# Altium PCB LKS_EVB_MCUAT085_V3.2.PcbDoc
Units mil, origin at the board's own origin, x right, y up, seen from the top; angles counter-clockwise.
Board outline 2625 x 1560 mil, 2 copper layers (Top Layer, Bottom Layer); 67 components, 81 nets, 250 pads, 65 vias.
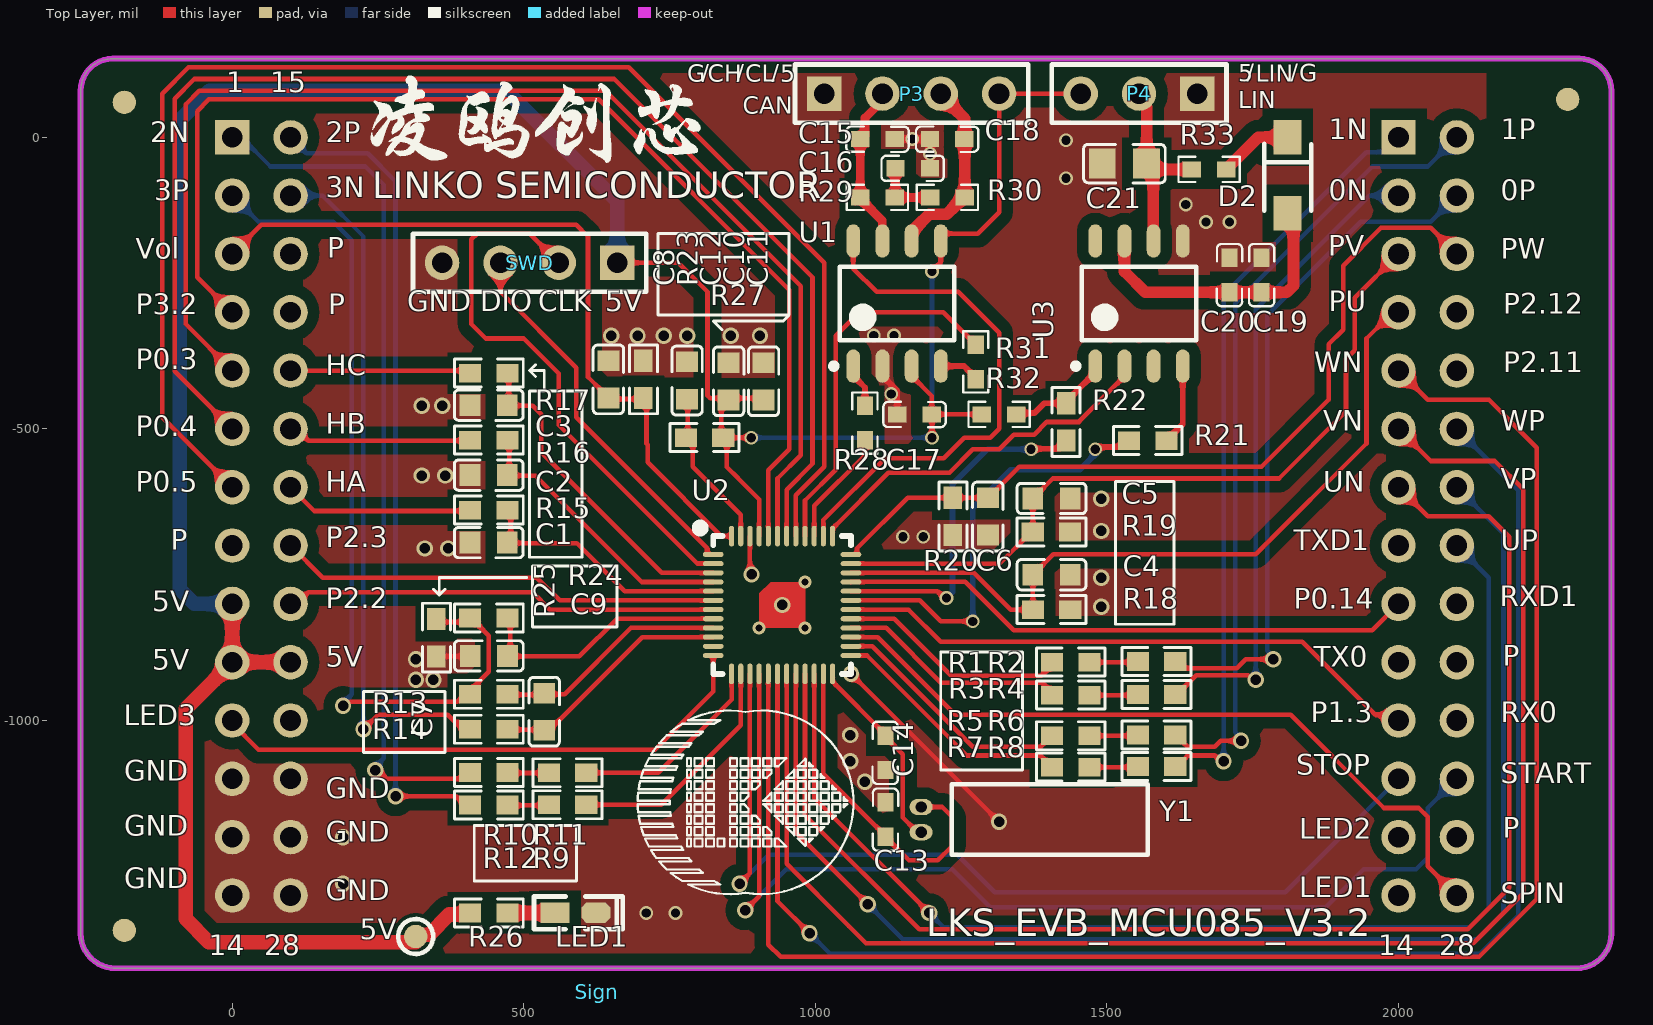
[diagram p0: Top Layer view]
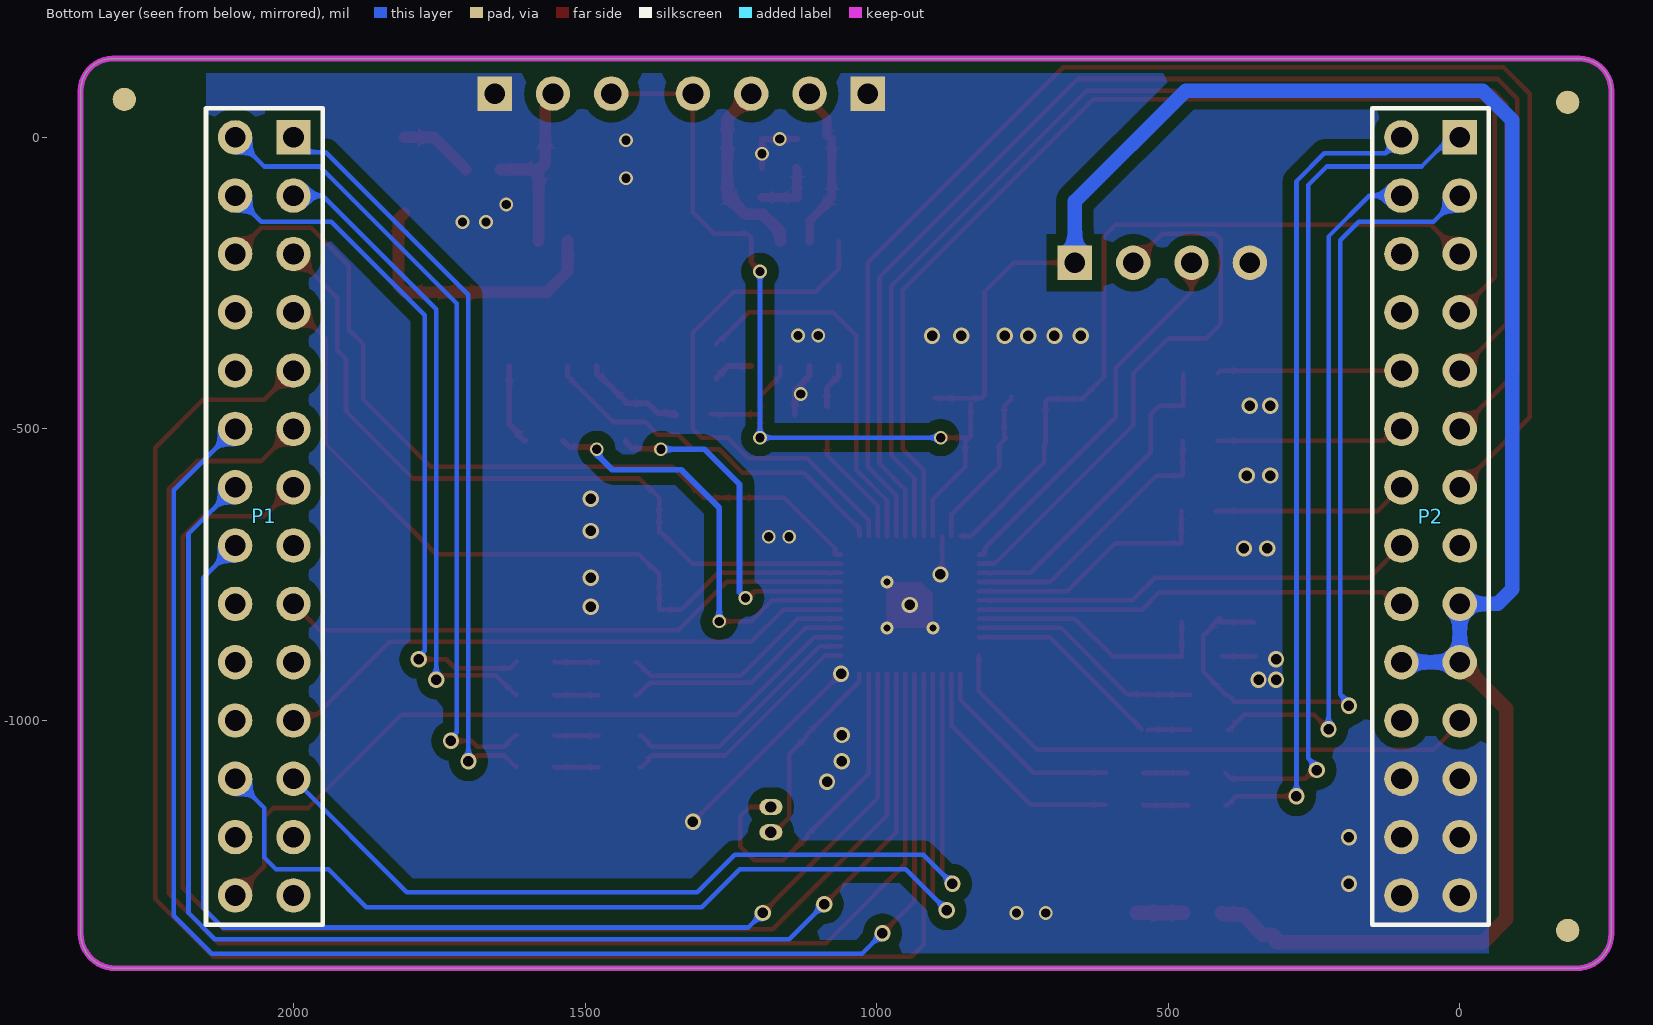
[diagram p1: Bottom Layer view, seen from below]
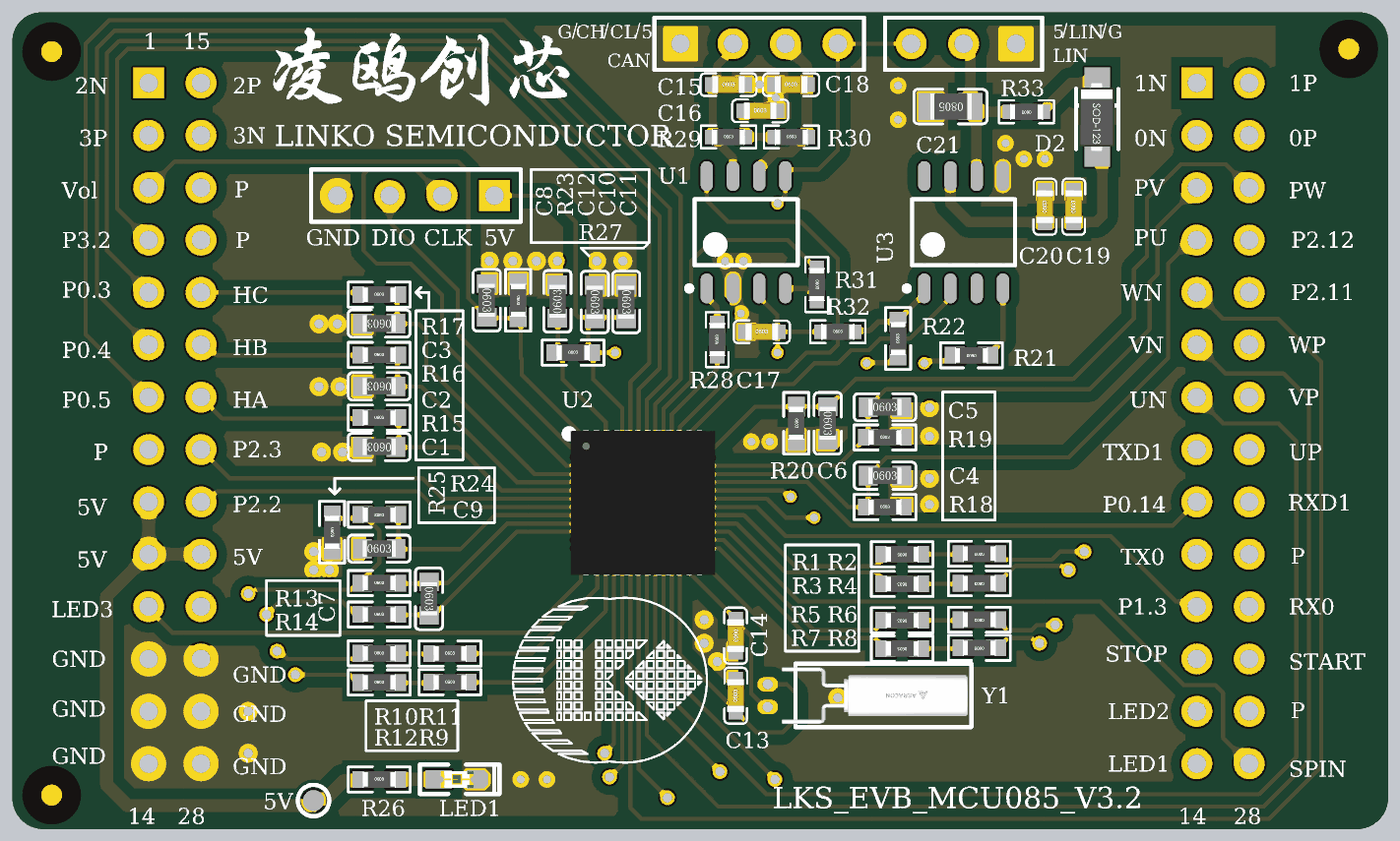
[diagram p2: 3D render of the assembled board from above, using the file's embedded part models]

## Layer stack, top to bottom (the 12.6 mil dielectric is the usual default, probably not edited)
Top Solder: solder mask 0.4, Solder Resist, Dk 3.5
Top Layer: signal copper 1.4
Dielectric1: dielectric 12.6, FR-4, Dk 4.8
Bottom Layer: signal copper 1.4
Bottom Solder: solder mask 0.4, Solder Resist, Dk 3.5

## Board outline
-260,-1365 ccw(c-200,-1365) -200,-1425 2305,-1425 ccw(c2305,-1365) 2365,-1365 2365,80 ccw(c2310,80) 2310,135 -205,135 ccw(c-205,80) -260,80

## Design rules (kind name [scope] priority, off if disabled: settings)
Clearance Clearance_2 [InPolygon] p1: gap=20 ignorepadtopadclearanceinfootprint=FALSE except(0: Arc-Hole Track-Hole SMDPad-Hole THPad-Hole Via-Hole Fill-Hole Poly-Hole Region-Hole Text-Hole)
Clearance Clearance_1 [All] p2: gap=4 ignorepadtopadclearanceinfootprint=FALSE except(0: Arc-Hole Track-Hole SMDPad-Hole THPad-Hole Via-Hole Fill-Hole Poly-Hole Region-Hole Text-Hole)
ComponentClearance [All] p1: gap=0 collisioncheckmode=3 verticalgap=0 showdistances=FALSE
FabricationTestpoint [(IsPad And (OnTopLayer Or OnBottomLayer))] p1: side=3 testpointundercomponent=TRUE minsize=40 maxsize=100 preferedsize=60 minholesize=0 maxholesize=40 preferedholesize=32 testpointgrid=1 allowsidetop=TRUE allowsidebottom=TRUE usegrid=TRUE gridtolerance=0.01
HoleSize [All] p1: absolutevalues=TRUE maxlimit=100 minlimit=0 maxpercent=80.000 minpercent=20.000
PolygonConnect [All] p1: connectstyle=Direct reliefconductorwidth=10 reliefentries=4 polygonreliefangle="90 Angle" airgapwidth=10
RoutingVias [All] p1: holewidth=28 width=50 viastyle="Through Hole" minholewidth=0 minwidth=10 maxholewidth=28 maxwidth=50
SilkToSolderMaskClearance SilkscreenOverComponentPads [IsPad] p1: minsilkscreentomaskgap=10 clearancetoexposedcopper=TRUE
SolderMaskExpansion [All] p1: expansion=4 istentingtop=FALSE
Width [All] p1: maxlimit=100 minlimit=3.94 preferedwidth=7.87
26 further rules are at their usual default settings.

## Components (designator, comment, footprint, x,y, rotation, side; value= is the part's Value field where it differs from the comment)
5V "TestP" TP-40 315,-1370 r0 top
C1 "10nF/16V" 0603C 439.85,-694.97 r180 top
C2 "10nF/16V" 0603C 439.85,-579.25 r180 top
C3 "10nF/16V" 0603C 439.85,-459.25 r180 top
C4 "1nF/16V" 0603C 1405,-750 r0 top
C5 "1nF/16V" 0603C 1405,-619.25 r0 top
C6 "1nF/16V" 0603C 1295.75,-650 r270 top
C7 "1nF/16V" 0603C 535,-985 r270 top
C8 "100nF/50V" 0603C 645,-415 r270 top
C9 "1nF/16V" 0603C 439.98,-889.25 r0 top
C10 "10uF/10V" 0603C 851.24,-418.31 r270 top
C11 "100nF/50V" 0603C 911.24,-418.31 r270 top
C12 "100nF/50V" 0603C 780,-417 r90 top
C13 "4.7nF/50V" "0603C _1" 1120,-1170 r90 top
C14 "4.7nF/50V" "0603C _1" 1120,-1055.47 r270 top
C15 "30pF" "0603C _1" 1106.43,-3 r0 top
C16 "4.7nF/50V" "0603C _1" 1166.91,-53 r0 top
C17 "100nF" "0603C _1" 1170,-475 r0 top
C18 "30pF" "0603C _1" 1225.96,-3 r0 top
C19 "2.2uF/25V" "0603C _1" 1765.08,-236.22 r90 top
C20 "100nF" "0603C _1" 1710.08,-236.22 r90 top
C21 "1nF" 0805C 1530,-45 r180 top
D2 "1N4148" SOD123 1810,-65 r90 top
LED1 "LED" "LED 0603R" 588.51,-1330 r0 top
P1 "Header 14X2A" HDR2X14_CEN 2000,0 r270 bottom
P2 "Header 14X2A" HDR2X14_CEN 0,0 r270 bottom locked
P3 "Header 4" HDR1X4 1015,75 r0 top
P4 "Header 3" HDR1X3 1655,75 r180 top
R1 "20K1%" 0603R 1437.85,-900 r180 top value=K
R2 "20K1%" 0603R 1585,-898.83 r180 top value=K
R3 "20K1%" 0603R 1437.85,-956.59 r180 top value=K
R4 "20K1%" 0603R 1585,-955.42 r180 top value=K
R5 "20K1%" 0603R 1437.85,-1026.17 r180 top value=K
R6 "20K1%" 0603R 1585,-1025 r180 top value=K
R7 "20K1%" 0603R 1437.85,-1080 r180 top value=K
R8 "20K1%" 0603R 1585,-1078.83 r180 top value=K
R9 "20K1%" 0603R 575.01,-1144.52 r0 top value=K
R10 "20K1%" 0603R 440,-1144.85 r0 top value=K
R11 "20K1%" 0603R 575.01,-1089.56 r0 top value=K
R12 "20K1%" 0603R 440,-1089.25 r0 top value=K
R13 "1K1%" 0603R 440,-955 r0 top value=K
R14 "1K1%" 0603R 440,-1015 r0 top value=K
R15 "2K" 0603R 440,-639.25 r0 top value=K
R16 "2K" 0603R 440,-519.25 r0 top value=K
R17 "2K" 0603R 440,-404.25 r0 top value=K
R18 "1K1%" 0603R 1405,-810 r0 top value=K
R19 "1K1%" 0603R 1404.85,-676.86 r0 top value=K
R20 "1K1%" 0603R 1235.75,-650 r270 top value=K
R21 "10R" 0603R 1570,-520 r180 top value=K
R22 "10R" 0603R 1430,-488 r90 top value=K
R23 "1K1%" 0603R 705,-415 r270 top value=K
R24 "1K1%" 0603R 440,-824.25 r180 top value=K
R25 "10R" 0603R 350,-858 r270 top value=K
R26 "330R" 0603R 440,-1330 r0 top value=330
R27 "20K1%" 0603R 810,-515 r0 top value=K
R28 "10R" 0603R_1 1085,-490 r90 top value=K
R29 "60R/1%" 0603R_1 1106.43,-103 r0 top value=K
R30 "60R/1%" 0603R_1 1226.43,-103 r0 top value=K
R31 "10R" 0603R_1 1275,-385 r270 top value=K
R32 "10K" 0603R_1 1315,-475 r0 top value=K
R33 "1K" 0603R_1 1675,-55 r180 top value=K
Sign "LKS_sign" LKS_LOGO2 625,-1465 r0 top
SWD "Header 4" HDR1X4 660,-215.05 r180 top
U1 "SIT1051T/3" SOP-8N 1140,-285 r90 top
U2 "LKS32AT85C8Q9" LKS085-QFN48 942.87,-801.89 r0 top
U3 "SIT1027Q" SOP-8N 1555,-285 r90 top
Y1 "WTL3T45412LZ" DT-38 1445,-1170 r180 top (schematic designator Y?)

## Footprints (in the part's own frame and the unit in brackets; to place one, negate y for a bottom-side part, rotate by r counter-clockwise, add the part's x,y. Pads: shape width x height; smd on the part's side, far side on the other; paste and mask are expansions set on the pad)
0603C [mm]
  rect 0.9x0.95 smd: 1(-0.813,0) 2(0.813,0)
  silkscreen extent -1.5,-0.66 1.5,0.66, body extent -0.8,-0.4 0.8,0.4, height 0.45
"0603C _1" [mm]
  rect 0.8x0.7 smd: 1(-0.75,0) 2(0.75,0)
  silkscreen extent -1.36,-0.56 1.36,0.55, body extent -0.8,-0.41 0.8,0.41, height 0.81
0603R [mil]
  rect 38x32 smd: 1(-32,0) 2(32,0)
  silkscreen extent -59,-24 59,24, body extent -31,-16 32,16, height 16
0603R_1 [mm]
  rect 0.8x0.7 smd: 1(-0.75,0) 2(0.75,0)
  silkscreen extent -1.33,-0.55 1.33,0.55, body extent -0.8,-0.4 0.8,0.4, height 0.4
0805C [mil]
  rect 46x51.18 smd: 1(-38,0) 2(38,0)
  silkscreen extent -70,-33 70,33, body extent -40,-25 38,25, height 22
DT-38 [mm]
  oval 1x0.7 hole 0.5 paste+0 mask+0: 1(6.7,0.55) 2(6.7,-0.55)
  silkscreen extent -3.18,-1.55 5.36,1.52, body extent -3.2,-1.85 6.73,1.85, height 0.25
HDR1X3 [mm] "Connector; Header; 3 Position"
  rect 1.5x1.5 hole 0.9: 1(0,0)
  round 1.5 hole 0.9: 2(2.54,0) 3(5.08,0)
  silkscreen extent -1.27,-1.27 6.35,1.27
HDR1X4 [mm] "Connector; Header; 4 Position"
  rect 1.5x1.5 hole 0.9: 1(0,0)
  round 1.5 hole 0.9: 2(2.54,0) 3(5.08,0) 4(7.62,0)
  silkscreen extent -1.27,-1.27 8.89,1.27
HDR2X14_CEN [mm] "Connector; Header; 14x2 Position"
  rect 1.5x1.5 hole 0.9: 1(0,0)
  round 1.5 hole 0.9: 2(2.54,0) 3(5.08,0) 4(7.62,0) 5(10.16,0) 6(12.7,0) 7(15.24,0) 8(17.78,0) 9(20.32,0) 10(22.86,0) 11(25.4,0) 12(27.94,0) 13(30.48,0) 14(33.02,0) 15(0,-2.54) 16(2.54,-2.54) 17(5.08,-2.54) 18(7.62,-2.54) 19(10.16,-2.54) 20(12.7,-2.54) 21(15.24,-2.54) 22(17.78,-2.54) 23(20.32,-2.54) 24(22.86,-2.54) 25(25.4,-2.54) 26(27.94,-2.54) 27(30.48,-2.54) 28(33.02,-2.54)
  silkscreen extent -1.27,-3.81 34.29,1.27
"LED 0603R" [mil] "红色0"
  rect 50x35 smd: 1(-35,0.26)
  oct 50x35 smd: 2(35,0.26)
  silkscreen extent -71,-28 81,28, body extent -31,-16 31,16, height 18
LKS085-QFN48 [mm]
  round 0.025 smd: 0(0,0)
  oval 0.22x0.9 smd: 1(-2.2,3) 2(-1.8,3) 3(-1.4,3) 4(-1,3) 5(-0.6,3) 6(-0.2,3) 7(0.2,3) 8(0.6,3) 9(1,3) 10(1.4,3) 11(1.8,3) 12(2.2,3) 25(2.2,-3) 26(1.8,-3) 27(1.4,-3) 28(1,-3) 29(0.6,-3) 30(0.2,-3) 31(-0.2,-3) 32(-0.6,-3) 33(-1,-3) 34(-1.4,-3) 35(-1.8,-3) 36(-2.2,-3)
  oval 0.9x0.22 smd: 13(3,2.2) 14(3,1.8) 15(3,1.4) 16(3,1) 17(3,0.6) 18(3,0.2) 19(3,-0.2) 20(3,-0.6) 21(3,-1) 22(3,-1.4) 23(3,-1.8) 24(3,-2.2) 37(-3,-2.2) 38(-3,-1.8) 39(-3,-1.4) 40(-3,-1) 41(-3,-0.6) 42(-3,-0.2) 43(-3,0.2) 44(-3,0.6) 45(-3,1) 46(-3,1.4) 47(-3,1.8) 48(-3,2.2)
  Top Layer region: -1,-1 -1,0.5 -0.5,1 1,1 1,-1
  silkscreen extent -3.68,-3 3,3.47, body extent -3.51,-3.51 3.51,3.51, height 0.78
LKS_LOGO2 [mil]
  silkscreen extent 70,167 440,482
SOD123 [mm] "SOD-123; 2 Leads; Body 2.7 x 1.6 mm, (LxW)"
  rect 1.5x1.22 smd: 1(-1.65,0) 2(1.65,0)
  silkscreen extent -1.55,-1.03 1.38,1.02, body extent -1.93,-0.82 1.93,0.87, height 0.92
SOP-8N [mm]
  oval 1.45x0.6 smd: 1(-2.725,1.905) 2(-2.725,0.635) 3(-2.725,-0.635) 4(-2.725,-1.905) 5(2.725,-1.905) 6(2.725,-0.635) 7(2.725,0.635) 8(2.725,1.905)
  silkscreen extent -2.85,-2.5 1.6,2.88, body extent -2,-2.5 2,2.5, height 1.7
TP-40 [mil] "?"
  round 40 smd: 1(-0.39,-0.39)
  silkscreen extent -30,-30 30,30

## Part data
5V: "测试点"
C1 C2 C3 C4 C5 C6: library part CAP, "Capacitor"
C7 C8 C9 C10 C11 C12: library part C, "Capacitor"
C13 C14 C15 C16 C17 C18 C19 C20 C21: library part Capacitor, "Capacitor --贴片电容"
D2: library part Diode, "Default Diode", PackageDocument=Sep-1996
LED1: "发光二极管"
P1 P2: "Header, 14-Pin, Dual row"
P3 SWD: "Header, 4-Pin"
P4: "Header, 3-Pin"
R1 R2 R3 R4 R5 R6 R7 R8 R9 R10 R11 R12 R13 R14 R15 R16 R17 R18 R19 R20 R21 R22 R23 R24 R25 R26 R27 R28 R29 R30 R31 R32 R33: library part Res, "Resistor"
Sign: "凌鸥公司图标/丝印"
U1: "SIT芯力特CAN芯片  sop-8"
U2: library part LKS085, "车规芯片"
U3: library part SIT1021T, "SIT芯力特LIN芯片  SOP-8"
Y1: library part Crystal, "CRYSTAL 圆柱体晶振 频率：4MHz 频率公差：±20ppm 频率稳定度：±20ppm 负载电容：20pF 等效串联电阻(ESR)：150Ω 工作温度：-20℃~+70℃", Case/Package=Radial, ESR (Equivalent Series Resistance)=50kR, Frequency=32.768kHz, Frequency Stability=-0.034ppm, Frequency Tolerance=20ppm, Load Capacitance=12.5pF, Manufacturer=Abracon, Manufacturer Part Number=AB26TRB-32.768KHZ-T, Max Operating Temperature=85°C, Min Operating Temperature=-40°C, Operating Frequency="32.768 kHz", Package Quantity=500

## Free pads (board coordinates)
  round 40 all layers, no hole: 2(-185,-1360) 2(2290,65) 3(-185,60)

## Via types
v1: diameter 28, hole 18, Top Layer to Bottom Layer, 41 vias
v2: diameter 23.62, hole 15.75, Top Layer to Bottom Layer, 21 vias
v3: diameter 22, hole 12, Top Layer to Bottom Layer, 3 vias

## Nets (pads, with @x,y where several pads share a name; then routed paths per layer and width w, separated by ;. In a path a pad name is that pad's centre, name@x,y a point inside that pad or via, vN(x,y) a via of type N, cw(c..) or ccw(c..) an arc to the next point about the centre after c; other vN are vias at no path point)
+5V: 5V.1 C10.2 C11.2 C17.2 P2.9 P2.10 P2.24 P3.4 P4.3 R26.1 R27.2 R32.1 SWD.1 U1.3 U1.5 U2.4 | length 5338
  Top Layer w7.87: SWD.1 765.05,-215.05 815,-265 815,-442.75 819.61,-447.36 C11.2@901.24,-447.36 ; C10.2@838.84,-455.92 838.84,-512.38 848.2,-521.74 848.2,-565.33 867.5,-584.63 867.5,-585 903.51,-621 U2.4 ; R27.2 v2(890,-515) ; U1.3 1165,-409.02 1199.53,-443.54 C17.2 ; v2(1200,-515) 1200,-475.47 C17.2 ; v2(1200,-230) 1215,-215 U1.5 1215,-172.27 1222.27,-165 1278.64,-165 1315,-128.64 P3.4 P4.3 ; R32.1 C17.2
  Top Layer w25: P2.9 P2.10 ; P2.24 P2.10 ; 5V.1@314.61,-1380 -40,-1380 -80,-1340 -80,-980 P2.10 ; 5V.1@314.61,-1377.32 314.61,-1374.45 321.54,-1367.52 337.48,-1367.52 372.48,-1332.52 405.48,-1332.52 R26.1
  Bottom Layer w7.87: v2(890,-515) v2(1200,-515) v2(1200,-230)
  Bottom Layer w25: P2.24 P2.10 0,-814.64 -14.64,-800 -65,-800 -90,-775 -90,29.62 -39.62,80 470,80 660,-110 SWD.1
+15V: C19.1 C20.1 D2.1 U3.7 | length 490.2
  Top Layer w20: U3.7 1530,-230 1565.75,-265.75 C20.1 1808.28,-265.75 1820,-254.03 1820,-139.96 D2.1
CAN_RX: R31.1 U2.9 | length 646.3
  Top Layer w7.87: U2.9 982.25,-622.75 1035,-570 1035,-340 1075,-300 1219.53,-300 1263.19,-343.66 1265.16,-343.66 1275,-353.5 R31.1
CAN_TX: R28.1 U2.10 | length 200.3
  Top Layer w7.87: U2.10 997.99,-632.01 1085,-545 R28.1
CANH: C15.1 P3.2 R29.1 U1.7 | length 275.7
  Top Layer w15: C15.1 R29.1 1078.87,-103 1085.15,-109.28 1085.15,-113.21 1114.7,-142.76 1114.7,-177.42 U1.7 ; C15.1@1085.15,3.28 1085.15,33.23 1115,63.08 P3.2
CANL: C18.2 P3.3 R30.2 U1.6 | length 327.1
  Top Layer w20: U1.6@1164.31,-177.02 U1.6 1165,-161.96 1194.96,-132.01 1224.99,-132.01 1253.99,-103 R30.2 1255.96,-3 1255.96,31.78 1215,72.74 P3.3
GND: C1.2 C2.2 C3.2 C4.2 C5.2 C6.2 C8.1 C9.1 C10.1 C11.1 C12.2 C13.2 C14.2 C15.2 C16.2 C17.1 C18.1 C19.2 C20.2 C21.2 LED1.2 P2.12 P2.13 P2.14 P2.26 P2.27 P2.28 P3.1 P4.1 R18.2 R19.2 R20.2 R23.1 R25.2 SWD.4 U1.2 U2.0 U2.3 U3.5 | length 687.8
  Top Layer w3.94: v1@887.76,-746.77 v1(890.51,-749.53)
  Top Layer w7.8: v1@887.76,-746.77 U2.3
  Top Layer w7.87: R25.2 C9.1@408,-890 ; v1(1060.98,-920) 1061.05,-920 v1(1315,-1173.89) v1(1315,-1173.89)
  Top Layer w10: U1.2 1115,-409.02 1140.47,-434.49 C17.1 ; C15.2 v2(1166.2,-3) C18.1 C16.2
  other v1: 190,-1280 190,-1200 1085,-1105 1060,-1070 1060,-1025 315,-930 345,-930 315,-895 1490,-805 942.99,-801.88 1490,-755 330,-705 370,-705 1490,-675 1490,-620 325,-580 365,-580 325,-460 360,-460 650,-340 695,-340 740,-340 780,-340 855,-340 905,-340
  other v2: 710,-1330 760,-1330 1150,-685 1185,-685 1130,-440 1100,-340 1135,-340 1670,-145 1710,-145 1635,-115 1430,-70 1196.43,-28 1430,-5
  other v3: 903.51,-841.26 982.25,-841.26 982.25,-762.52
GND0: P2.16 R14.1 | length 1193
  Top Layer w7.87: v1(225,-1015) 250,-990 369.24,-990 395,-1015.75 R14.1@398,-1015.75
  Bottom Layer w7.87: P2.16 155,-100 225,-170 v1(225,-1015)
HALL_U: C1.1 R15.2 U2.44 | length 436.5
  Top Layer w7.87: R15.2@477.46,-640.72 477.46,-695.72 590.72,-695.72 673.27,-778.27 U2.44
HALL_V: C2.1 R16.2 U2.45 | length 485.4
  Top Layer w7.87: R16.2@475,-520 475,-580 520,-580 702.52,-762.52 U2.45
HALL_W: C3.1 R17.2 U2.46 | length 562.6
  Top Layer w7.87: R17.2@474.06,-405 474.06,-460 515,-460 530,-475 530,-540 736.77,-746.77 U2.46
HU: P2.21 R15.1 | length 335.3
  Top Layer w7.87: P2.21 140.72,-640.72 R15.1@418.41,-640.72
HV: P2.20 R16.1 | length 324.2
  Top Layer w7.87: P2.20 110.2,-500 130.2,-520 R16.1@415.94,-520
HW: P2.19 R17.1 | length 317.1
  Top Layer w7.87: P2.19 410,-400 R17.1@415,-405
INH: U3.8
LED1: P1.14
LED2: P1.13
LED3: P2.11 U2.37 | length 951.5
  Top Layer w7.87: P2.11 0,-1005 45,-1050 725,-1050 824.76,-950.24 U2.37
LIN: C21.1 P4.2 R33.2 U3.6 | length 330.5
  Top Layer w20: P4.2 1555,65 1568,52 C21.1 C21.1@1578,-55 ; U3.6 1579.31,-177.02 1579.31,-56.31 C21.1@1578,-55 ; R33.2 C21.1@1578,-55
NetC16_1: C16.1 R29.2 R30.1 | length 111.5
  Top Layer w15: C16.1 1136.67,-53.71 1136.67,-102.29 R29.2 R30.1
NetD2_2: D2.2 R33.1 | length 128.2
  Top Layer w20: R33.1 1759.49,-0.04 D2.2
NetLED1_1: LED1.1 R26.2 | length 79.6
  Top Layer w25: R26.2@474.13,-1329.87 LED1.1@534.88,-1329.87 ; LED1.1@535,-1329.74 LED1.1@534.88,-1329.87 ; LED1.1@553.51,-1329.87 LED1.1@534.88,-1329.87
NetR1_1: R1.1 R2.2 | length 75.8
  Top Layer w7.87: R1.1@1477.71,-900 1551.83,-900 R2.2
NetR3_1: R3.1 R4.2 | length 76.1
  Top Layer w7.87: R3.1@1477.42,-956.59 1551.83,-956.59 R4.2
NetR5_1: R5.1 R6.2 | length 76.8
  Top Layer w7.87: R5.1@1476.69,-1026.17 1551.83,-1026.17 R6.2
NetR7_1: R7.1 R8.2 | length 76.5
  Top Layer w7.87: R7.1@1477,-1080 1551.83,-1080 R8.2
NetR9_1: R9.1 R10.2 | length 77.5
  Top Layer w7.87: R10.2@465.98,-1145.6 541.94,-1145.6 R9.1
NetR11_1: R11.1 R12.2 | length 76.9
  Top Layer w7.87: R12.2@466.29,-1090 542.57,-1090 R11.1
NetR21_2: R21.2 U2.18 | length 739.5
  Top Layer w8: U2.18 1179.01,-794.01 1215,-830 v2(1270,-830)
  Top Layer w10: v2(1480,-535) 1483.69,-535 1487.69,-531 1527,-531 R21.2
  Bottom Layer w10: v2(1270,-830) 1270,-635 1335,-570 1453.45,-570 1480,-543.45 v2(1480,-535)
NetR22_1: R22.1 U2.17 | length 595.8
  Top Layer w8: U2.17 1209.04,-778.27 1220.77,-790 v2(1225,-790)
  Top Layer w10: v2(1370,-535) 1371,-534 1419,-534 1430,-523 R22.1
  Bottom Layer w10: v2(1225,-790) 1235,-780 1235,-595 1295,-535 v2(1370,-535)
NetR28_2: R28.2 U1.1 | length 76.5
  Top Layer w10: U1.1 1065,-409.02 1085,-429.02 R28.2
NetR31_2: R31.2 U1.4 | length 70.4
  Top Layer w10: U1.4 1254.72,-392.28 1275,-412.56 R31.2
NRST: C12.1 R27.1 U2.2 | length 284.7
  Top Layer w7.87: C12.1@769,-445.06 769,-449 781,-461 R27.1@781,-517.03 ; R27.1 790,-527 790,-565 872.01,-647.01 U2.2
OC: C9.2 R24.1 U2.41 | length 437.7
  Top Layer w7.87: C9.2@476.02,-890 540,-890 595.21,-890 660,-825.21 824.46,-825.21 U2.41 ; R24.1@476.78,-831.18 476.78,-891.18 C9.2@478.75,-891.18
OPA0_IN: R3.2 U2.21 | length 400.2
  Top Layer w7.87: U2.21 1121.26,-841.26 1215,-935 1388.83,-935 1410.42,-956.59 R3.2@1413.42,-956.59
OPA0_IP: R1.2 U2.20 | length 402.7
  Top Layer w7.87: U2.20 1135.51,-825.51 1233.13,-923.13 1387.58,-923.13 1410.71,-900 R1.2@1413.71,-900
OPA1_IN: R7.2 U2.24 | length 425.9
  Top Layer w7.87: U2.24 1088.5,-888.5 1260,-1060 1385.85,-1060 1390.79,-1064.94 1390.79,-1067.94 1402.85,-1080 R7.2
OPA1_IP: R5.2 U2.23 | length 425.3
  Top Layer w7.87: U2.23 1097.76,-872.76 1270,-1045 1386.18,-1045 1390.79,-1040.39 1390.79,-1038.23 1402.85,-1026.17 R5.2
OPA2_IN: R11.2 U2.36 | length 345.7
  Top Layer w7.87: R11.2@606.51,-1089.56 R11.2 730.64,-1089.56 856.26,-963.94 U2.36
OPA2_IP: R9.2 U2.35 | length 409.5
  Top Layer w7.87: R9.2 735.48,-1144.52 872.01,-1007.99 U2.35
OPA3_IN: C7.2 R14.2 U2.39 | length 418.7
  Top Layer w7.87: R14.2@462,-1015.75 533.75,-1015.75 C7.2 ; C7.2@545,-1015 702.99,-857.01 U2.39
OPA3_IP: C7.1 R13.2 U2.40 | length 410.2
  Top Layer w7.87: R13.2@462,-955.75 534.25,-955.75 535,-955 570,-955 683.74,-841.26 U2.40
OSC_IN: C14.1 U2.25 Y1.1 | length 338
  Top Layer w7.87: U2.25 1029.49,-933.47 1120,-1023.98 C14.1 1120,-1027.91 1150,-1057.91 1150,-1166.34 1175.31,-1191.65 Y1.1
OSC_OUT: C13.1 U2.26 Y1.2 | length 576.3
  Top Layer w7.87: 1013.74,-1023.9 1013.74,-1091.3 1120,-1197.56 C13.1 1120,-1201.5 1129.84,-1211.34 1131.81,-1211.34 1160.47,-1240 1210,-1240 1234,-1216 1234,-1164.61 1217.73,-1148.35 Y1.2
  Top Layer w8: 1013.74,-1023.9 U2.26
P0.3: P2.5 U2.6 | length 2138.4
  Top Layer w7.87: P2.5 -80,-320 -80,56.42 -56.42,80 640,80 975,-255 975,-545 935,-585 U2.6
P0.4: P2.6 U2.7 | length 2317.8
  Top Layer w7.87: P2.6 -98.75,-401.25 -98.75,66.25 -65,100 655,100 995,-240 995,-560 950.75,-604.25 U2.7
P0.5: P2.7 U2.8 | length 2506
  Top Layer w7.87: P2.7 -120,-480 -120,75 -75,120 680,120 1015,-215 1015,-565 966.5,-613.5 U2.8
P0.14: P1.9 U2.16 | length 992.1
  Top Layer w7.87: U2.16 1061.28,-762.22 1257.22,-762.22 1340,-845 1955,-845 P1.9
P1.3: P1.11 U2.19 | length 1017.8
  Top Layer w7.87: U2.19 1159.76,-809.76 1215,-865 1835,-865 1960.21,-990.21 1990.21,-990.21 P1.11
P2.2: P2.23 U2.42 | length 745.4
  Top Layer w7.87: P2.23 110.2,-800 130.2,-780 515,-780 544.76,-809.76 U2.42
P2.3: P2.22 U2.43 | length 763.7
  Top Layer w7.87: P2.22 155,-755 522.5,-755 561.51,-794.01 U2.43
P2.11: P1.19
P2.12: P1.18
P3.2: P2.4 U2.5 | length 1965.3
  Top Layer w7.87: P2.4 -60,-240 -60,45 -40,65 628.21,65 955,-261.79 955,-535 919.25,-570.75 U2.5
PGND: P2.2 R13.1 R24.2 R25.1 | length 1486.7
  Top Layer w7.87: v1(190,-975) 195.45,-975 202.63,-967.81 385.93,-967.81 398,-955.75 401,-955.75 440,-916.75 440,-855 425.06,-840.06 425.06,-837.06 413,-825 R24.2@410,-825 ; R25.1@352.73,-832.12 353.67,-831.18 R24.2@417.73,-831.18
  Bottom Layer w7.87: P2.2 45,-145 173.3,-145 205,-176.7 205,-955.32 190,-970.32 v1(190,-975)
PGND0: P1.2 R4.1 | length 1115.7
  Top Layer w7.87: R4.1 1620,-955.42 1653.18,-922.24 1741.8,-922.24 1749.55,-930 v1(1755,-930)
  Bottom Layer w7.87: v1(1755,-930) 1755,-295 1950,-100 P1.2
PGND1: P1.1 R8.1 | length 1306.8
  Top Layer w7.87: R8.1 1620,-1078.83 1638.84,-1059.99 1684.54,-1059.99 1694.55,-1070 v1(1700,-1070)
  Bottom Layer w7.87: v1(1700,-1070) 1700,-270 1944.41,-25.59 1974.41,-25.59 P1.1
PGND2: P2.1 R12.1 | length 1471
  Top Layer w7.87: v1(245,-1085) 250.45,-1085 265.45,-1100 392.29,-1100 R12.1@402.29,-1090
  Bottom Layer w7.87: P2.1 15.67,0 65.67,-50 228.3,-50 260,-81.7 260,-1064.55 245,-1079.55 v1(245,-1085)
PU: C4.1 P1.4 R18.1 U2.15 | length 1317.6
  Top Layer w7.87: U2.15 1271.77,-746.77 1335,-810 R18.1 C4.1 1373,-749.02 1386.78,-735.24 1387.76,-735.24 1408,-715 1755,-715 1945,-525 1945,-345 1990,-300 P1.4
PV: C5.1 P1.3 R19.1 U2.14 | length 1298.6
  Top Layer w7.87: U2.14 1315.68,-731.02 1369.85,-676.86 R19.1 1373,-676.71 C5.1 1373,-618.27 1386.78,-604.49 1387.76,-604.49 1407.25,-585 1795,-585 1910,-470 1910,-380 1925,-365 1925,-275 P1.3
PW: C6.1 P1.17 R20.1 U2.13 | length 1415.4
  Top Layer w7.87: U2.13 1070.57,-715.28 1071.3,-714.55 1071.3,-704.96 1158.26,-618 R20.1 C6.1 1296.73,-618 1349.73,-565 1765,-565 1880,-450 1880,-355 1905,-330 1905,-220 1970,-155 2055,-155 P1.17
RXD0: R22.2 R32.2 U3.1 | length 189.9
  Top Layer w10: R32.2@1353.04,-475.93 1343.59,-475.93 R32.2 1346.55,-472.97 1375.28,-472.97 1392.25,-456 R22.2 1430,-453 1471.38,-411.62 1473.71,-411.62 1480,-405.33 U3.1
SLP_N: U2.12 U3.2 | length 639.2
  Top Layer w8: U2.12 1029.49,-670.79 1125.28,-575 1230,-575 1270,-535 1315,-535 1340,-510 1375,-510 1397,-488 1452,-488 1530,-410 U3.2
SPIN: P1.28 U2.22 | length 1272.3
  Top Layer w7.87: U2.22 1107.01,-857.01 1240,-990 1815,-990 1975,-1150 2035,-1150 2050,-1165 2050,-1250 P1.28
START1: P1.26 U2.33 | length 1833
  Top Layer w7.87: v1(879.48,-1325.52) 903.5,-1301.5 U2.33
  Bottom Layer w7.87: v1(879.48,-1325.52) 950,-1255 1235,-1255 1300,-1320 1875,-1320 1940,-1255 2030,-1255 2050,-1235 2050,-1150 P1.26
STB: U1.8 U2.11 | length 901.3
  Top Layer w7.87: U2.11 1013.74,-656.26 1120,-550 1220,-550 1255,-515 1300,-515 1315,-500 1315,-335 1245,-265 1105,-265 1065,-225 U1.8
STOP1: P1.12 U2.34 | length 1625.4
  Top Layer w7.87: v1(870,-1280) 887.76,-1262.24 U2.34
  Bottom Layer w7.87: v1(870,-1280) 920,-1230 1243.21,-1230 1307.74,-1294.53 1805.47,-1294.53 P1.12
SWCLK: SWD.2 U2.47 | length 956.6
  Top Layer w7.87: SWD.2 509.95,-165 420,-165 410,-175 410,-240 410,-320 435,-345 500,-345 560,-405 560,-493.3 797.42,-730.72 824.54,-730.72 U2.47@824.77,-730.94
SWDIO: SWD.3 U2.48 | length 656.8
  Top Layer w7.87: SWD.3 460,-265 590,-395 590,-480 814.71,-704.71 814.71,-714.55 815.43,-715.28 U2.48
TXD0: R21.1 U3.4 | length 141.1
  Top Layer w10: R21.1 1605,-520 1616,-509 1616,-506 1630,-492 U3.4
UN: P1.7 U2.28 | length 2387.6
  Top Layer w7.87: U2.28 982.24,-1162.24 1178.19,-1358.19 2118.4,-1358.19 2190,-1286.59 2190,-685 2155,-650 2050,-650 P1.7
UP: P1.22 U2.27 | length 2120.2
  Top Layer w7.87: U2.27 997.99,-1132.99 v1(1195,-1330)
  Bottom Layer w7.87: v1(1195,-1330) 1220,-1355 2121.59,-1355 2155,-1321.59 2155,-755 P1.22
UP-: P2.15 R10.1 | length 1394.5
  Top Layer w7.87: v1(280,-1130) 383.38,-1130 398.98,-1145.6 R10.1@401.98,-1145.6
  Bottom Layer w7.87: P2.15 127.17,-27.17 232.17,-27.17 280,-75 v1(280,-1130)
VN: P1.6 U2.30 | length 2629.7
  Top Layer w7.87: U2.30 950.75,-1245.75 1057.5,-1352.5 1086.81,-1381.81 2128.19,-1381.81 2213.62,-1296.38 2213.62,-603.62 2165,-555 2055,-555 P1.6
VOL_ADC: C8.2 P2.3 R23.2 U2.1 | length 1301.6
  Top Layer w7.87: P2.3 50,-150 590,-150 610,-170 610,-410.94 632.75,-433.7 645.79,-446.73 645.79,-448.7 705.63,-448.7 706.42,-447.91 710.39,-451.89 710.39,-525.39 712.2,-527.2 712.2,-557.2 838.78,-683.78 U2.1
VP: P1.21 U2.29 | length 2342.8
  Top Layer w7.87: U2.29 966.5,-1191.5 v1(1090,-1315)
  Bottom Layer w7.87: v1(1090,-1315) 1150,-1375 2135,-1375 2180,-1330 2180,-680 P1.21
VP-: P1.15 R6.1 | length 1378.7
  Top Layer w7.87: R6.1 1620,-1025 1632.06,-1037.06 1632.06,-1038.92 1638.14,-1045 1685,-1045 1695,-1035 v1(1730,-1035)
  Bottom Layer w7.87: v1(1730,-1035) 1730,-1030.32 1720,-1020.32 1720,-285 1955,-50 2050,-50 P1.15
WAKE_N: U3.3
WN: P1.5 U2.32 | length 2898.2
  Top Layer w7.87: U2.32 919.25,-1384.25 940.43,-1405.43 2137.97,-1405.43 2237.24,-1306.16 2237.24,-532.07 2155.17,-450 2050,-450 P1.5
WP: P1.20 U2.31 | length 2602.7
  Top Layer w7.87: U2.31 935,-1310 v1(990,-1365)
  Bottom Layer w7.87: v1(990,-1365) 1025,-1400 2140,-1400 2205,-1335 2205,-605 P1.20
WP-: P1.16 R2.1 | length 1183.2
  Top Layer w7.87: R2.1 1628.53,-910.37 1722.79,-910.37 1738.16,-895 v1(1785,-895)
  Bottom Layer w7.87: v1(1785,-895) 1785,-890.32 1775,-880.32 1775,-305 1935,-145 2055,-145 P1.16
pads on no net: P1.8 P1.10 P1.23 P1.24 P1.25 P1.27 P2.8 P2.17 P2.18 P2.25 U2.38

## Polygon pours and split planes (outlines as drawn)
GND on Bottom Layer "GND_L02_P001" (solid, remove dead copper, pour order 1): -50,-1430.01 2150,-1430.01 2150,140.02 -50,140.02
GND on Top Layer "GND_L01_P000" (solid, remove dead copper, pour order 0): -50,-1430.01 2150,-1430.01 2150,140.02 -50,140.02

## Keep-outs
Keep-Out Layer:
  the board outline again, w10

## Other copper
Top Layer:
  pour cut-out: 824.76,-683.78 1060.99,-683.78 1060.99,-919.94 1061.05,-920 824.77,-920

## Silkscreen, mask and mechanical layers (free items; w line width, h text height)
Top Overlay:
  drawing of 50 lines, arcs and shapes, not listed
  text "/" at 1740,90 h50
  text "/" at 1815,90 h50
  text "/" at 805,89.71 h50
  text "/" at 865,89.71 h50
  text "/" at 925,89.71 h50
  text "G" at 780.05,85.46 h50
  text "CH" at 815.05,85.46 h50
  text "CL" at 880.05,85.46 h50
  text "5" at 940,85.46 h50
  text "5" at 1725,85.75 h50
  text "LIN" at 1755.05,85.29 h50
  text "G" at 1830.05,85.75 h50
  text "LIN" at 1725.05,40 h50
  text "CAN" at 875.05,30.46 h50
  text "1N" at 1880,-15 h60
  text "1P" at 2175.06,-15 h60
  text "2N" at -140.66,-20 h60
  text "2P" at 160,-20 h60
  text "3N" at 159.94,-115 h60
  text "3P" at -133.55,-120 h60
  text "0N" at 1880,-120 h60
  text "0P" at 2175,-120 h60
  text "PV" at 1879.66,-215 h60
  text "P" at 163.34,-218.25 h60
  text "Vol" at -165.89,-220 h60
  text "PW" at 2175.06,-220 h60
  text "GND" at 300,-310 h60
  text "DIO" at 425,-310 h60
  text "CLK" at 525,-310 h60
  text "5V" at 640,-310 h60
  text "PU" at 1880.11,-310 h60
  text "P3.2" at -165.83,-315 h60
  text "P" at 165,-315 h60
  text "P2.12" at 2179.73,-314.52 h60
  text "P0.3" at -165.83,-410 h60
  text "WN" at 1855.24,-415 h60
  text "P2.11" at 2179.73,-414.52 h60
  text "HC" at 160,-420 h60
  text "VN" at 1870.51,-515 h60
  text "WP" at 2175.06,-515 h60
  text "HB" at 160,-520 h60
  text "P0.4" at -165.83,-525 h60
  text "VP" at 2175,-615 h60
  text "P0.5" at -165.83,-620 h60
  text "HA" at 160,-620 h60
  text "UN" at 1870.89,-620 h60
  text "P2.3" at 160,-714.52 h60
  text "P" at -105.64,-719.52 h60
  text "TXD1" at 1820,-720 h60
  text "UP" at 2175,-720 h60
  text "RXD1" at 2173.52,-816.38 h60
  text "P2.2" at 160,-819.52 h60
  text "P0.14" at 1820,-820 h60
  text "5V" at -137.33,-825 h60
  text "P" at 2178.34,-918.25 h60
  text "5V" at 159.94,-920 h60
  text "TX0" at 1854.24,-920 h60
  text "5V" at -137.33,-925 h60
  text "P1.3" at 1849.19,-1015 h60
  text "RX0" at 2175.06,-1015 h60
  text "LED3" at -185.83,-1020 h60
  text "STOP" at 1825,-1105 h60
  text "GND" at -185,-1115 h60
  text "START" at 2175,-1120 h60
  text "GND" at 160,-1145 h60
  text "GND" at -185,-1210 h60
  text "P" at 2178.34,-1213.25 h60
  text "LED2" at 1830,-1215 h60
  text "GND" at 160,-1220 h60
  text "GND" at -185,-1300 h60
  text "LED1" at 1830,-1315 h60
  text "GND" at 160,-1320 h60
  text "SPIN" at 2175,-1325 h60
  text "LKS_EVB_MCU085_V3.2" at 1190,-1385 h80
Top Solder:
  circle w77.95: c-185,-1360 r17.01
  circle w77.99: c-185,60 r17.01
  circle w77.95: c2290,65 r17.01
